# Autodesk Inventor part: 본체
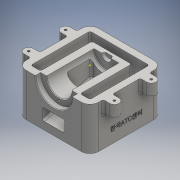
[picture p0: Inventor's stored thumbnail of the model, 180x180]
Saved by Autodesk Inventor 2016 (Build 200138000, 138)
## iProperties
Created: 2022-03
Part Number: 본체
Material: 일반
Document SubType Name: Modeling
Designer: CAD01
Density: 1 g/cm^3
Appearance: 기본값
Author: CAD01
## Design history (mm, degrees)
sketch "스케치1"
  geometry: L1 (-55, -55)-(55, -55); L2 (55, -55)-(55, 55); L3 (55, 55)-(-55, 55); L4 (-55, 55)-(-55, -55); L5 (-55, -55)-(55, 55); L6 (55, -55)-(-55, 55); 1 further point
  constraints: 12 end point, 2 midpoint, 2 parallel, 1 horizontal, 1 perpendicular
  dimensions: "d0" = 110 distance of L3.end L2.end; "d1" = 110 distance of L2.end L1.end
extrude "돌출1" new body sketch "스케치1" distance "d2" = 65; taper "d3" = 0 deg
sketch "스케치2"
  geometry: L1 (-55, 65)-(-55, 37); L2 (-55, 0)-(-55, 65) reference; L3 (-47, 37)-(-47, 65); L4 (-55, 37)-(-47, 37); L5 (-55, 65)-(55, 65) reference; L6 (55, 65)-(-55, 65); L7 (-47, 46)-(25, 46); L8 (25, 46)-(25, 65); 1 further point
  constraints: 12 end point, 4 point on line, 2 horizontal, 1 perpendicular, 1 vertical
  dimensions: "d4" = 8 distance of L1.end L3.start; "d5" = 28 distance of L1.start L1.end; "d6" = 72 distance of L7.start L7.end; "d8" = 19 distance between parallel lines of L7 L5
revolve "회전1" sketch "스케치2" stored, may be unused: angle "d10" = 90 deg
sketch "스케치3"
  geometry: L1 (-30, 45)-(-30, -45); L2 (-55, 55)-(-55, -55) reference; L3 (-45, -45)-(-45, 45); L4 (-45, 45)-(45, 45); L5 (55, 55)-(-55, 55) reference; L6 (45, 45)-(45, -45); L7 (55, -55)-(55, 55) reference; L8 (30, 45)-(30, -45); L9 (-45, 33)-(45, 33); L10 (-45, -45)-(45, -45); L11 (28, -55)-(55, -55) reference; 1 further point
  constraints: 14 end point, 6 point on line, 4 vertical, 3 horizontal
  dimensions: "d11" = 25 distance between parallel lines of L2 L1; "d12" = 10 distance between parallel lines of L2 L3; "d13" = 10 distance between parallel lines of L5 L4; "d14" = 10 distance between parallel lines of L7 L6; "d15" = 25 distance between parallel lines of L7 L8; "d16" = 22 distance between parallel lines of L5 L9; "d17" = 10 distance between parallel lines of L11 L10
extrude "돌출2" cut sketch "스케치3" stored distance "d18" = 65; taper "d19" = 0 deg
sketch "스케치4"
  geometry: L1 (33, 0)-(33, 65) reference; L2 (33, 0)-(33, 30); L3 (33, 30)-(-45, 9.1); L4 (19, 31.425)-(-55, 11.597); L5 (-19, 38.843)-(-55, 29.197); L6 (19, 65)-(-19, 65); L7 (-55, 37)-(-55, 65) reference; L8 (19, 65)-(19, 31.425); L9 (-19, 65)-(-19, 38.843); L10 (-55, 0)-(-55, 65) reference; L11 (-55, 11.597)-(-55, 29.197); L12 (-47, 37)-(-47, 65) reference; L13 (55, 0)-(55, 65) reference; L14 (-45, 0)-(33, 0) reference; L15 (-45, 0)-(-45, 9.1) reference; L16 (-47, 65)-(25, 65); L17 (-45, 65)-(45, 65) reference; 2 further points
  constraints: 22 end point, 6 point on line, 3 horizontal, 3 parallel, 2 midpoint, 2 vertical
  dimensions: "d20" = 30 distance of L1.start L2.end; "d21" = 75 deg angle of L1 L3; "d22" = 5 distance between parallel lines of L3 L4; "d23" = 17 distance between parallel lines of L4 L5; "d24" = 38 distance of L6.start L6.end; "d25" = 36 distance from line of L7 L6.end
extrude "돌출3" cut sketch "스케치4" stored distance "d26" = 34; taper "d27" = 0 deg
sketch "스케치5"
  geometry: L1 (55, 55)-(-55, 55) reference; L2 (0, 77)-(0, -77) reference; L3 (-55, 55)-(-55, -55); L4 (-65, 28)-(-65, 21); L5 (-65, 21)-(-55, 21); L6 (-65, 28)-(-65, 35); L7 (-65, 35)-(-55, 35); A1 r 7 centre (-65, 28) between (-65, 21) and (-65, 35); 1 further point
  constraints: 10 end point, 3 vertical, 2 horizontal, 2 point on circle, 2 point on line, 1 centre point
  dimensions: "d28" = 14 diameter of A1; "d29" = 27 distance from line of L1 L4.start; "d30" = 65 distance from line of L4.start L2
extrude "돌출4" join sketch "스케치5" distance "d31" = 20; taper "d32" = 0 deg
sketch "스케치6"
  geometry: C1 r 1 at (65, -28); A1 r 7 centre (65, -28) between (65, -35) and (65, -21) reference; 1 further point
  constraints: 1 centre point, 1 concentric
  dimensions: "d36" = 2 diameter of C1
hole "구멍1" sketch "스케치6" at (65, -28) diameter "d37" = 3.459; stored, may be unused: countersink angle "d41" = 90 deg, drill point angle "d43" = 118 deg; dims "d38" = 9, "d39" = 4, "d40" = 2, "d42" = 11
sketch "스케치7"
  geometry: L1 (0, 77)-(0, -77) reference; L2 (-19, 25)-(19, 25) reference; L3 (-7.5, 25)-(-5.191, 29); L4 (7.5, 25)-(5.191, 29); L5 (-5.191, 29)-(5.191, 29); L6 (-7.5, 25)-(7.5, 25); L7 (0, 29)-(0, 25); 1 further point
  constraints: 10 end point, 3 point on line, 2 midpoint, 1 collinear, 1 horizontal
  dimensions: "d52" = 30 deg angle of L1 L4; "d53" = 60 deg angle of L4 L3; "d55" = 4 distance between parallel lines of L2 L5; "d56" = 15 distance of L4.start L3.start; "d57" = 7.5 distance from line of L1 L3.start
revolve "회전2" sketch "스케치7" stored, may be unused: angle "d58" = 90 deg
extrude "돌출5" cut sketch "스케치4" stored distance "d59" = 20; taper "d60" = 0 deg
extrude "돌출6" cut sketch "스케치4" stored distance "d61" = 20; taper "d62" = 0 deg
sketch "스케치8" dims "d66" = 46
  geometry: L1 (30, 0)-(-30, 0) reference; L2 (0, -23)-(0, 0); 1 further point
  constraints: 2 end point, 1 midpoint, 1 vertical, 1 vertical alignment, 2 other
hole "구멍2" sketch "스케치8" at (0, -23) diameter "d67" = 3.459; stored, may be unused: countersink angle "d71" = 90 deg, drill point angle "d73" = 118 deg; dims "d68" = 9, "d69" = 4, "d70" = 2, "d72" = 11
fillet "모깎기1" dims "d74" = 3
fillet "모깎기2" dims "d75" = 3
fillet "모깎기3" dims "d76" = 3
fillet "모깎기4" dims "d77" = 3
sketch "스케치9"
  geometry: 1 further point
fillet "모깎기5" dims "d78" = 3
fillet "모깎기6" dims "d79" = 3
fillet "모깎기7" dims "d80" = 3
fillet "모깎기8" dims "d81" = 3
sketch "스케치10"
  geometry: L1 (0, 0)-(-65, 0) reference; L2 (0, 0)-(0, 110) reference; 2 further points
  constraints: 1 other
  dimensions: "d82" = 55 distance from line of L1 point (-20, 55); "d83" = 20 distance from line of L2 point (-20, 55)
feature "엠보싱1" sketch "스케치10" dims "d84" = 0.5, "d85" = 0
fillet "모깎기9" dims "d86" = 13
fillet "모깎기10" dims "d87" = 3
fillet "모깎기11" dims "d88" = 1
chamfer "모따기2" distance "d89" = 1; stored, may be unused: second distance "d90" = 2, angle "d91" = 45 deg
node "솔리드1"
pattern_linear "직사각형 패턴1" dims "d35" = 56
mirror "대칭1"
pattern_linear "직사각형 패턴2" dims "d46" = 56
